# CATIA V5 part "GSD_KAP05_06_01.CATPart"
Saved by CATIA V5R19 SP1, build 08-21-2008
Part number: GSD_POLYLINE_02
Definition: Beispielmodell: Polyline erzeugen
Description: CATIA V5 Flächenmodellierung  Copyright (c) 2009 Maik Hertha IT Consultants
Bounding box of the stored display mesh (mm): x 0 to 37.698, y 0 to 84.917, z 20 to 20
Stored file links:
  C:\Users\Maik\CAD Daten\modelle\gsd_buch_uebung\GSD_KAP05_06_01.CATPart
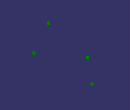
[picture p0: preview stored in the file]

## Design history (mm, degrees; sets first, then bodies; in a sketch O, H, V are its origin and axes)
Set1
  Plane1: type Equation, A 0, B 0, C 1, Length 20
  Point1: type OnPlane, Support Plane1, Direction (1, 0, 0), H 37.698, V 21.194
  Point2: type OnPlane, Support Plane1, Direction (1, 0, 0), H 11.807, V 56.176
  Point3: type OnPlane, Support Plane1, Direction (1, 0, 0), H 34.918, V 84.917
  Point4: type OnPlane, Support Plane1, Direction (1, 0, 0), H 0, V 0
Body1 (main body)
